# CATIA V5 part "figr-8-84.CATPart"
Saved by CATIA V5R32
Part number: Part1
Bounding box of the stored display mesh (mm): x -44.701 to 35.128, y -35.23 to 15.392, z -47.191 to 31.322
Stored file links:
  D:\PROJECTS\Project 2022\CATIA V5 6R 2022\Resources\Part Files\c08_catia_v5_6r2022_prt\figr-8-84.CATPart
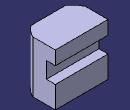
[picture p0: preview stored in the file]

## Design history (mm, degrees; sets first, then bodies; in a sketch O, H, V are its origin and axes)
Body1 (main body)
  Sketch1 on xy-plane, origin (0, 0, 0), H (1, 0, 0), V (0, 1, 0)
    line L1 (-44.7013, 25.8759) -> (35.1284, 25.8759)
    line L2 (35.1284, 25.8759) -> (35.1284, -18.9612)
    line L3 (-44.7013, 25.8759) -> (-44.7013, -18.9612)
    arc A1 centre (-4.7865, 1.0752) radius 44.6615 from (-44.7013, -18.9612) to (35.1284, -18.9612) ccw
    horizontal: L1 H
    vertical: L2 V, L3 V
  Sketch2 on yz-plane, origin (0, 0, 0), H (0, 1, 0), V (0, 0, 1)
    line L1 (-35.2302, 31.3221) -> (-35.2302, -47.1914)
    point P2 (-35.2302, -47.1914)
    point P3 (-35.2302, -47.1914)
    line L2 (-35.2302, -47.1914) -> (15.3919, -47.1914)
    point P4 (15.3919, -47.1914)
    line L3 (15.3919, 31.3221) -> (-35.2302, 31.3221)
    line L4 (15.3919, 31.3221) -> (15.3919, 10.6589)
    line L5 (15.3919, 10.6589) -> (1.7321, 10.6589)
    line L6 (1.7321, 10.6589) -> (1.7321, -13.9018)
    line L7 (1.7321, -13.9018) -> (15.3919, -13.9018)
    point P9 (15.3919, -13.9018)
    line L8 (15.3919, -13.9018) -> (15.3919, -47.1914)
    point P10 (15.3919, -47.1914)
    vertical: L1 V, L4 V, L6 V, L8 V
    horizontal: L2 H, L3 H, L5 H, L7 H
    coincidence: P9 L4, P10 L2, P10 P4, P3 P2
  SolidCombine1: FirstComponentDirection Sketch1, FirstComponentProfile Sketch1, SecondComponentDirection Sketch2, SecondComponentProfile Sketch2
